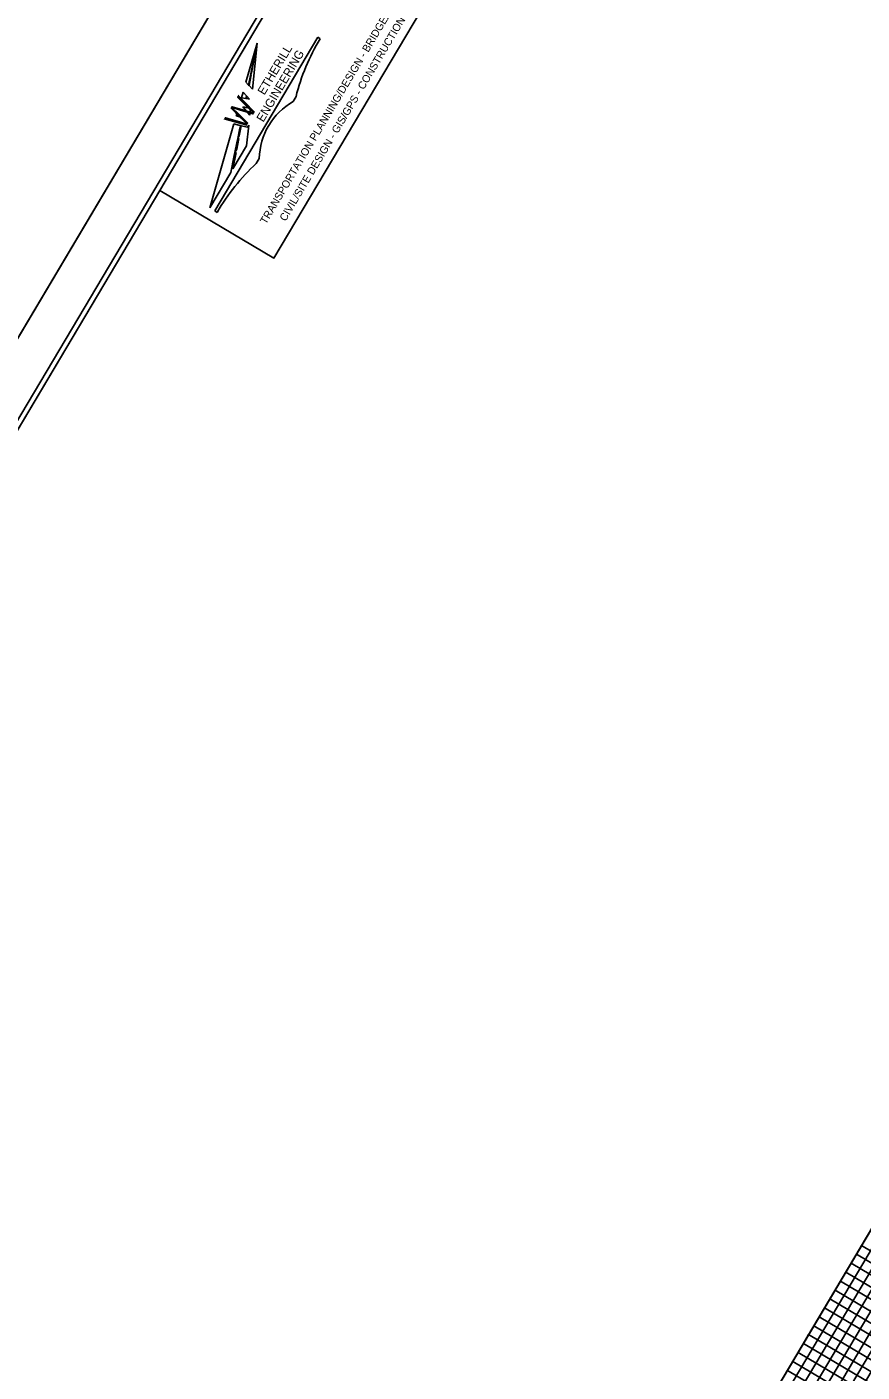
# Model space of a CAD drawing. Extents: x 2138768 to 2143723, y 406633 to 414335.
# Drawn here: x 2141534 to 2141936, y 411305 to 411953 of the extents above; entities that cross this region are included whole.
import ezdxf

# ---------------------------------------------------------------- set-up
doc = ezdxf.new("R2010")
doc.units = 0
for name, color, linetype in [('Default', 7, 'Continuous'), ('Sheet Clip Boundary CELL', 7, 'Continuous'), ('Sheet Cutting Line CELL', 7, 'Continuous'), ('Sheet DOT Grid CELL', 7, 'Continuous'), ('Sheet Layout Profile Border Port 2', 7, 'Continuous'), ('Sheet Plan And Profile CELL', 7, 'Continuous'), ('Sheet Plot Border Inside CELL', 7, 'Continuous'), ('Sheet Plot Border Outside CELL', 7, 'Continuous'), ('Sheet Profile Grid Major CELL', 7, 'Continuous'), ('Sheet Profile Grid Middle CELL', 7, 'Continuous'), ('Sheet Profile Grid Minor CELL', 7, 'Continuous')]:
    doc.layers.add(name, color=color, linetype=linetype)

msp = doc.modelspace()

# ---------------------------------------------------------------- linework, layer by layer
at = {"layer": 'Default'}
for p, q in [((2141624.24, 411864.6), (2141673.87, 411948.2)), ((2141644.7, 411945.32), (2141639.3, 411926.56)), ((2141644.7, 411945.32), (2141642.41, 411923.18)), ((2141644.56, 411944.63), (2141644.7, 411945.32)), ((2141644.57, 411944.64), (2141644.7, 411945.32)), ((2141673.87, 411948.2), (2141675.06, 411947.49)), ((2141641.7, 411930.66), (2141642.96, 411936.81)), ((2141641.95, 411931.08), (2141643.11, 411937.05)), ((2141643.09, 411937.46), (2141642.96, 411936.81)), ((2141642.96, 411936.81), (2141643.11, 411937.05)), ((2141643.09, 411937.46), (2141643.67, 411940.28)), ((2141643.23, 411937.69), (2141643.09, 411937.46)), ((2141643.23, 411937.69), (2141643.76, 411940.43)), ((2141640.58, 411925.17), (2141641.52, 411929.75)), ((2141640.77, 411924.96), (2141641.78, 411930.19)), ((2141641.7, 411930.66), (2141641.52, 411929.75)), ((2141641.52, 411929.75), (2141641.78, 411930.19)), ((2141641.95, 411931.08), (2141641.7, 411930.66)), ((2141639.3, 411926.56), (2141640.58, 411925.17)), ((2141640.77, 411924.96), (2141640.58, 411925.17)), ((2141642.41, 411923.18), (2141640.77, 411924.96)), ((2141637.14, 411919.08), (2141637.91, 411921.73)), ((2141637.14, 411919.08), (2141639.26, 411918.74)), ((2141639.53, 411920.05), (2141637.91, 411921.73)), ((2141639.26, 411918.74), (2141639.53, 411920.05)), ((2141639.56, 411918.69), (2141639.26, 411918.74)), ((2141639.77, 411919.79), (2141639.53, 411920.05)), ((2141639.77, 411919.79), (2141639.56, 411918.69)), ((2141639.56, 411918.69), (2141641.07, 411918.45)), ((2141641.07, 411918.45), (2141639.77, 411919.79)), ((2141663.4, 411919.69), (2141661.98, 411917.3)), ((2141634.66, 411910.45), (2141635, 411911.63)), ((2141636.28, 411909.96), (2141634.66, 411910.45)), ((2141635, 411911.63), (2141636.28, 411909.96)), ((2141637.85, 411914.69), (2141638.41, 411914.57)), ((2141638.32, 411914.12), (2141637.85, 411914.69)), ((2141638.41, 411914.57), (2141638.32, 411914.12)), ((2141638.32, 411914.12), (2141638.61, 411913.77)), ((2141638.41, 411914.57), (2141638.75, 411914.5)), ((2141638.61, 411913.77), (2141638.75, 411914.5)), ((2141641.12, 411910.73), (2141638.61, 411913.77)), ((2141638.75, 411914.5), (2141641.45, 411913.96)), ((2141641.45, 411913.96), (2141641.12, 411910.73)), ((2141621.86, 411866.01), (2141633.51, 411906.46)), ((2141633.51, 411906.46), (2141637.03, 411905.6)), ((2141635.31, 411899.42), (2141636.33, 411904.42)), ((2141636.09, 411900.74), (2141637.03, 411905.6)), ((2141636.09, 411900.74), (2141637.03, 411905.6)), ((2141637.03, 411905.6), (2141636.33, 411904.42)), ((2141637.03, 411905.6), (2141639.99, 411904.88)), ((2141640.62, 411905.92), (2141639.58, 411895.87)), ((2141639.99, 411904.88), (2141640.62, 411905.92)), ((2141633.94, 411892.73), (2141635.06, 411898.19)), ((2141634.84, 411894.25), (2141635.86, 411899.54)), ((2141635.06, 411898.19), (2141635.86, 411899.54)), ((2141635.31, 411899.42), (2141635.06, 411898.19)), ((2141636.09, 411900.74), (2141635.31, 411899.42)), ((2141631.96, 411883.03), (2141633.63, 411891.22)), ((2141639.58, 411895.87), (2141633.02, 411884.82)), ((2141633.02, 411884.82), (2141634.56, 411892.78)), ((2141633.63, 411891.22), (2141634.56, 411892.78)), ((2141634.56, 411892.78), (2141633.63, 411891.22)), ((2141633.63, 411891.22), (2141634.56, 411892.78)), ((2141633.94, 411892.73), (2141633.63, 411891.22)), ((2141634.84, 411894.25), (2141633.94, 411892.73)), ((2141645.68, 411889.83), (2141644.26, 411887.44)), ((2141631.96, 411883.03), (2141621.86, 411866.01)), ((2141625.44, 411863.89), (2141624.24, 411864.6))]:
    msp.add_line(p, q, dxfattribs=at)
msp.add_lwpolyline([(2141597.82, 411874.49), (2141700.1, 412046.82), (2141755.05, 412014.21), (2141652.77, 411841.88)], close=True, dxfattribs=at)
for centre, radius, start, end in [((2141757.15, 411896.72), 96.52, 148.26576, 166.23637), ((2141678.37, 411889), 32.7, 120.07272, 178.54602), ((2141711.94, 411814.06), 99.83, 132.68134, 150.05254)]:
    msp.add_arc(centre, radius, start, end, dxfattribs=at)
at = {"layer": 'Sheet Clip Boundary CELL'}
msp.add_lwpolyline([(2141532.03, 410686.07), (2141538.88, 410697.63), (2142265.12, 411921.19), (2142261.89, 411923.11), (2142271.94, 411940.04), (2141951.44, 412130.26), (2141849.34, 411958.24), (2141755.05, 412014.21), (2141652.77, 411841.88), (2141597.82, 411874.49), (2141065.92, 410978.35)], close=True, dxfattribs=at)
at = {"layer": 'Sheet Cutting Line CELL'}
msp.add_line((2141791.54, 412244.96), (2140932.27, 410797.26), dxfattribs=at)
at = {"layer": 'Sheet DOT Grid CELL'}
for p, q in [((2141509.57, 410648.23), (2142275.17, 411938.13)), ((2141917.89, 411336.18), (2142326.36, 411093.74))]:
    msp.add_line(p, q, dxfattribs=at)
at = {"layer": 'Sheet Layout Profile Border Port 2'}
msp.add_lwpolyline([(2141535.09, 410691.23), (2142249.65, 411895.14), (2142658.12, 411652.69), (2141943.55, 410448.78)], close=True, dxfattribs=at)
at = {"layer": 'Sheet Plan And Profile CELL'}
msp.add_lwpolyline([(2141802.21, 412218.85), (2141036.6, 410928.95), (2141939.53, 410393.03), (2142705.14, 411682.93)], close=True, dxfattribs=at)
at = {"layer": 'Sheet Plot Border Inside CELL'}
msp.add_lwpolyline([(2141863.34, 410259.75), (2142713.67, 411692.4), (2141806.44, 412230.88), (2140956.1, 410798.23)], close=True, dxfattribs=at)
at = {"layer": 'Sheet Plot Border Outside CELL'}
msp.add_lwpolyline([(2141873.9, 410238.36), (2142733.16, 411686.06), (2141791.54, 412244.96), (2140932.27, 410797.26)], close=True, dxfattribs=at)
at = {"layer": 'Sheet Profile Grid Major CELL'}
for points in [[(2141509.57, 410648.23), (2142275.17, 411938.13)], [(2142300.84, 411050.74), (2141892.37, 411293.18), (2141917.89, 411336.18), (2142326.36, 411093.74)]]:
    msp.add_lwpolyline(points, dxfattribs=at)
at = {"layer": 'Sheet Profile Grid Middle CELL'}
msp.add_line((2141531.06, 410635.47), (2142296.67, 411925.37), dxfattribs=at)
msp.add_lwpolyline([(2142313.6, 411072.24), (2141905.13, 411314.68), (2141930.65, 411357.68), (2142339.12, 411115.23)], dxfattribs=at)
at = {"layer": 'Sheet Profile Grid Minor CELL'}
for points in [[(2141543.68, 410686.12), (2142258.25, 411890.03), (2142253.95, 411892.58), (2141539.38, 410688.67)], [(2141552.28, 410681.02), (2142266.85, 411884.93), (2142262.55, 411887.48), (2141547.98, 410683.57)], [(2141565.18, 410673.36), (2142279.75, 411877.27), (2142275.45, 411879.82), (2141560.88, 410675.91)], [(2142341.67, 411119.53), (2141933.2, 411361.98), (2141935.75, 411366.28), (2142344.22, 411123.83)], [(2142334.01, 411106.63), (2141925.54, 411349.08), (2141928.1, 411353.38), (2142336.57, 411110.93)], [(2142328.91, 411098.04), (2141920.44, 411340.48), (2141922.99, 411344.78), (2142331.46, 411102.34)], [(2142321.25, 411085.14), (2141912.78, 411327.58), (2141915.34, 411331.88), (2142323.81, 411089.44)], [(2142316.15, 411076.54), (2141907.68, 411318.98), (2141910.23, 411323.28), (2142318.7, 411080.84)], [(2142308.49, 411063.64), (2141900.02, 411306.08), (2141902.58, 411310.38), (2142311.05, 411067.94)]]:
    msp.add_lwpolyline(points, dxfattribs=at)

# ---------------------------------------------------------------- texts
at = {"layer": 'Default'}
for s, height, p in [('TRANSPORTATION PLANNING/DESIGN - BRIDGE/STRUCTURE DESIGN', 3.674, (2141648.98, 411857.85)), ('CIVIL/SITE DESIGN - GIS/GPS - CONSTRUCTION OBSERVATION', 3.674, (2141658.38, 411859.3)), ('ENGINEERING', 4.1665, (2141647.64, 411907.05)), ('ETHERILL', 4.167, (2141648.17, 411920.1)), ('W', 11.11, (2141638.05, 411902.9))]:
    msp.add_text(s, height=height, rotation=59.30926, dxfattribs=at).set_placement(p)

doc.saveas('drawing.dxf')
